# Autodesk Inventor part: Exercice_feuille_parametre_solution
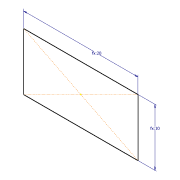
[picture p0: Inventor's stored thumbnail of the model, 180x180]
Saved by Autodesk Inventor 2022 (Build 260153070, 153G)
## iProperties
Created: 2021-06
Part Number: Exercice_feuille_parametre_solution
Material: Générique
Document SubType Name: Modeling
Designer: Fabian
Density: 1 g/cm^3
Appearance: Par défaut
Author: Fabian
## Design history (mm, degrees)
sketch "Esquisse1"
  geometry: L1 (-14.466, -7.233)-(14.466, -7.233); L2 (14.466, -7.233)-(14.466, 7.233); L3 (14.466, 7.233)-(-14.466, 7.233); L4 (-14.466, 7.233)-(-14.466, -7.233); L5 (-14.466, -7.233)-(14.466, 7.233); L6 (14.466, -7.233)-(-14.466, 7.233); 1 further point
  constraints: 12 end point, 2 midpoint, 2 parallel, 1 horizontal, 1 perpendicular
  dimensions: "Longueur" = 27.38613 dimension on L2.end L3.end (computed from Surface); "Largeur" = 13.69306 dimension on L1.end L2.end (= 0.5 x Longueur)
other parameters: "Surface" = 37.5 [user parameter; used in 1 equation term]
